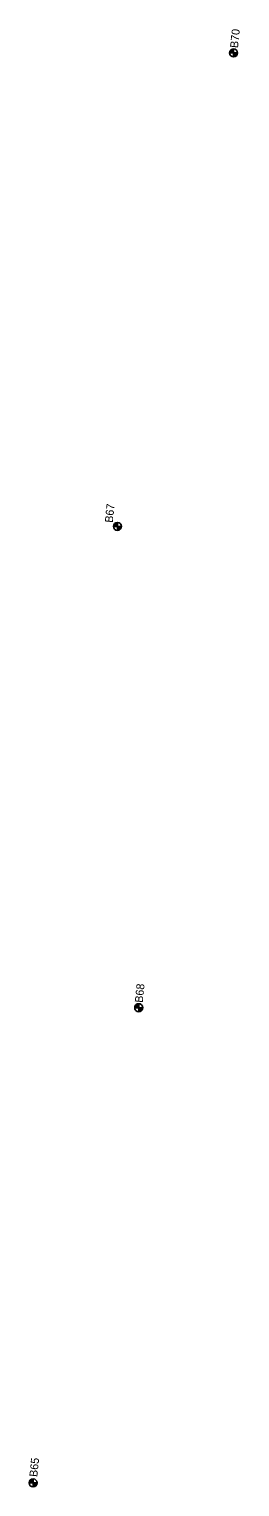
# Model space of a CAD drawing. Extents: x 335726 to 369746, y 119154 to 200788.
# Drawn here: x 359410 to 359673, y 166462 to 168282 of the extents above; entities that cross this region are included whole.
import ezdxf

# ---------------------------------------------------------------- set-up
doc = ezdxf.new("R2010")
doc.units = 0
for name, color, linetype in [('E_SOIL_BORE1 [KAPUR_CADDS_LEVELS]', 7, 'Continuous'), ('E_SOIL_BORE2 [KAPUR_CADDS_LEVELS]', 7, 'Continuous'), ('P_MARK', 7, 'Continuous')]:
    doc.layers.add(name, color=color, linetype=linetype)

msp = doc.modelspace()

# ---------------------------------------------------------------- linework, layer by layer
at = {"layer": 'P_MARK'}
for p, q in [((359665.4, 168257.8), (359665.4, 168247.8)), ((359660.4, 168252.8), (359670.4, 168252.8)), ((359515.3, 167661.3), (359525.3, 167661.3)), ((359520.3, 167666.3), (359520.3, 167656.3)), ((359541.8, 167060.1), (359551.8, 167060.1)), ((359546.8, 167065.1), (359546.8, 167055.1)), ((359415, 166471.5), (359415, 166461.5)), ((359410, 166466.5), (359420, 166466.5))]:
    msp.add_line(p, q, dxfattribs=at)
for centre in [(359665.4, 168252.8), (359520.3, 167661.3), (359546.8, 167060.1), (359415, 166466.5)]:
    msp.add_circle(centre, 5, dxfattribs=at)
for centre, radius, start, end in [((359665.4, 168252.8), 4.5, 89.9869, 179.9869), ((359665.4, 168252.8), 4, 89.9869, 179.9869), ((359665.4, 168252.8), 3.5, 89.9869, 179.9869), ((359665.4, 168252.8), 3, 89.9869, 179.9869), ((359665.4, 168252.8), 2.5, 89.9869, 179.9869), ((359665.4, 168252.8), 2, 89.9869, 179.9869), ((359665.4, 168252.8), 1.5, 89.9869, 179.9869), ((359665.4, 168252.8), 1, 89.9869, 179.9869), ((359665.4, 168252.8), 0.5, 89.9869, 179.9869), ((359665.4, 168252.8), 4.5, 269.9869, 359.9869), ((359665.4, 168252.8), 4, 269.9869, 359.9869), ((359665.4, 168252.8), 3.5, 269.9869, 359.9869), ((359665.4, 168252.8), 3, 269.9869, 359.9869), ((359665.4, 168252.8), 2.5, 269.9869, 359.9869), ((359665.4, 168252.8), 2, 269.9869, 359.9869), ((359665.4, 168252.8), 1.5, 269.9869, 359.9869), ((359665.4, 168252.8), 1, 269.9869, 359.9869), ((359665.4, 168252.8), 0.5, 269.9869, 359.9869), ((359520.3, 167661.3), 4.5, 89.9869, 179.9869), ((359520.3, 167661.3), 4, 89.9869, 179.9869), ((359520.3, 167661.3), 3.5, 89.9869, 179.9869), ((359520.3, 167661.3), 3, 89.9869, 179.9869), ((359520.3, 167661.3), 2.5, 89.9869, 179.9869), ((359520.3, 167661.3), 2, 89.9869, 179.9869), ((359520.3, 167661.3), 1.5, 89.9869, 179.9869), ((359520.3, 167661.3), 1, 89.9869, 179.9869), ((359520.3, 167661.3), 0.5, 89.9869, 179.9869), ((359520.3, 167661.3), 4.5, 269.9869, 359.9869), ((359520.3, 167661.3), 4, 269.9869, 359.9869), ((359520.3, 167661.3), 3.5, 269.9869, 359.9869), ((359520.3, 167661.3), 3, 269.9869, 359.9869), ((359520.3, 167661.3), 2.5, 269.9869, 359.9869), ((359520.3, 167661.3), 2, 269.9869, 359.9869), ((359520.3, 167661.3), 1.5, 269.9869, 359.9869), ((359520.3, 167661.3), 1, 269.9869, 359.9869), ((359520.3, 167661.3), 0.5, 269.9869, 359.9869), ((359546.8, 167060.1), 4.5, 89.9869, 179.9869), ((359546.8, 167060.1), 4, 89.9869, 179.9869), ((359546.8, 167060.1), 3.5, 89.9869, 179.9869), ((359546.8, 167060.1), 3, 89.9869, 179.9869), ((359546.8, 167060.1), 2.5, 89.9869, 179.9869), ((359546.8, 167060.1), 2, 89.9869, 179.9869), ((359546.8, 167060.1), 1.5, 89.9869, 179.9869), ((359546.8, 167060.1), 1, 89.9869, 179.9869), ((359546.8, 167060.1), 0.5, 89.9869, 179.9869), ((359546.8, 167060.1), 4.5, 269.9869, 359.9869), ((359546.8, 167060.1), 4, 269.9869, 359.9869), ((359546.8, 167060.1), 3.5, 269.9869, 359.9869), ((359546.8, 167060.1), 3, 269.9869, 359.9869), ((359546.8, 167060.1), 2.5, 269.9869, 359.9869), ((359546.8, 167060.1), 2, 269.9869, 359.9869), ((359546.8, 167060.1), 1.5, 269.9869, 359.9869), ((359546.8, 167060.1), 1, 269.9869, 359.9869), ((359546.8, 167060.1), 0.5, 269.9869, 359.9869), ((359415, 166466.5), 4.5, 89.9869, 179.9869), ((359415, 166466.5), 4, 89.9869, 179.9869), ((359415, 166466.5), 3.5, 89.9869, 179.9869), ((359415, 166466.5), 3, 89.9869, 179.9869), ((359415, 166466.5), 2.5, 89.9869, 179.9869), ((359415, 166466.5), 2, 89.9869, 179.9869), ((359415, 166466.5), 1.5, 89.9869, 179.9869), ((359415, 166466.5), 1, 89.9869, 179.9869), ((359415, 166466.5), 0.5, 89.9869, 179.9869), ((359415, 166466.5), 4.5, 269.9869, 359.9869), ((359415, 166466.5), 4, 269.9869, 359.9869), ((359415, 166466.5), 3.5, 269.9869, 359.9869), ((359415, 166466.5), 3, 269.9869, 359.9869), ((359415, 166466.5), 2.5, 269.9869, 359.9869), ((359415, 166466.5), 2, 269.9869, 359.9869), ((359415, 166466.5), 1.5, 269.9869, 359.9869), ((359415, 166466.5), 1, 269.9869, 359.9869), ((359415, 166466.5), 0.5, 269.9869, 359.9869)]:
    msp.add_arc(centre, radius, start, end, dxfattribs=at)

# ---------------------------------------------------------------- texts
at = {"layer": 'E_SOIL_BORE1 [KAPUR_CADDS_LEVELS]'}
for s, p in [('B70', (359670.8, 168258.5)), ('B67', (359514.4, 167665.5)), ('B68', (359551.8, 167065.9))]:
    msp.add_text(s, height=10, rotation=84.1728, dxfattribs=at).set_placement(p)
at = {"layer": 'E_SOIL_BORE2 [KAPUR_CADDS_LEVELS]'}
msp.add_text('B65', height=10, rotation=84.1728, dxfattribs=at).set_placement((359420.1, 166473.6))

doc.saveas('drawing.dxf')
